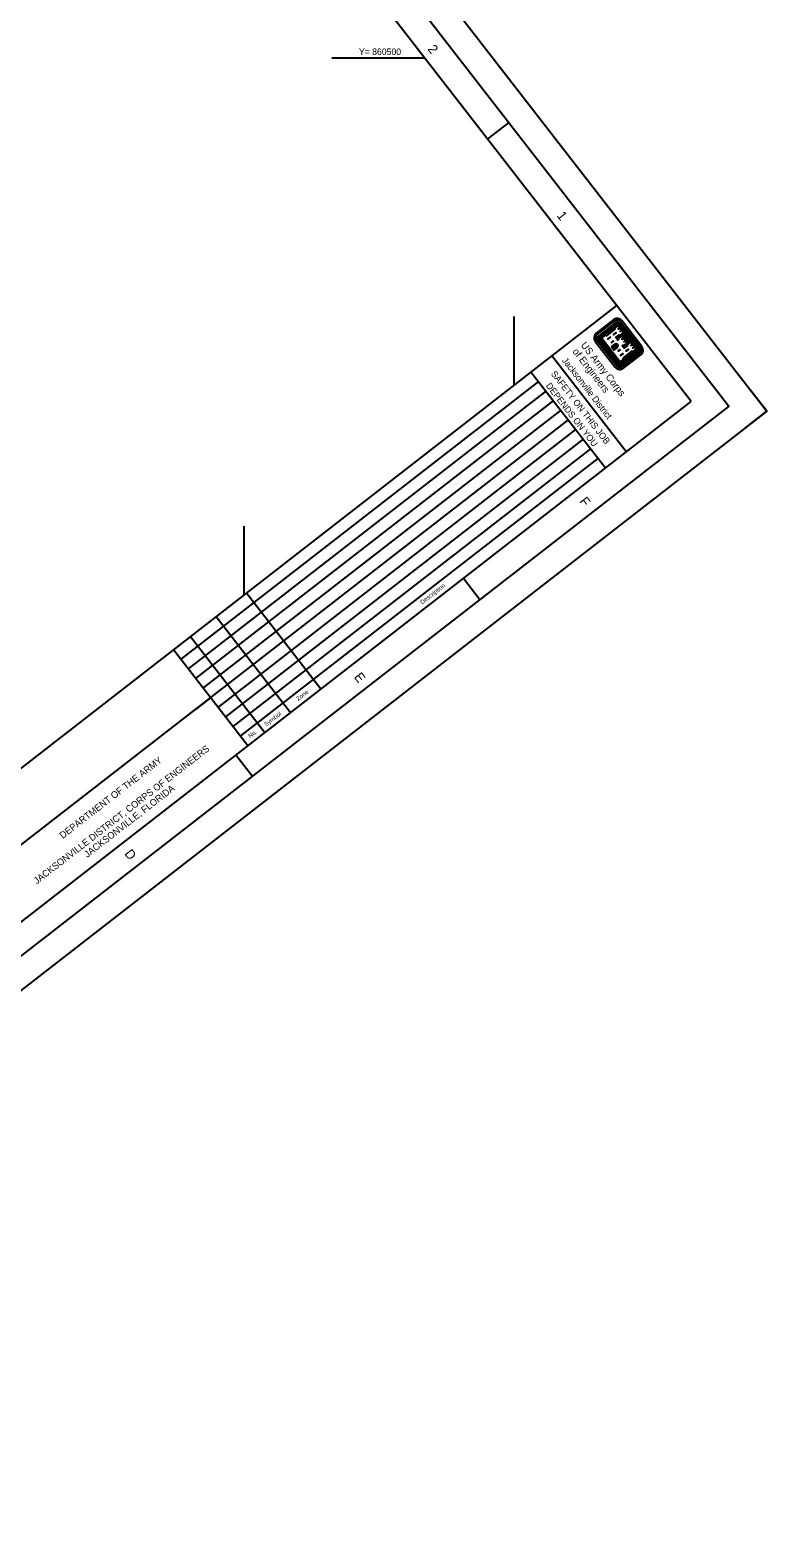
# Model space of a CAD drawing. Extents: x 575584 to 580968, y 857761 to 863322.
# Drawn here: x 579604 to 580968, y 857761 to 860551 of the extents above; entities that cross this region are included whole.
import ezdxf

# ---------------------------------------------------------------- set-up
doc = ezdxf.new("R2010")
doc.units = 0
for name, color, linetype in [('G-ANNO-NPLT', 7, 'Continuous'), ('G-ANNO-TEXT-LOGO', 7, 'Continuous'), ('G-ANNO-TEXT-TTLB', 7, 'Continuous'), ('G-ANNO-TTLB', 7, 'Continuous'), ('V-TOPO-COOR-STAT', 7, 'Continuous')]:
    doc.layers.add(name, color=color, linetype=linetype)

msp = doc.modelspace()

# ---------------------------------------------------------------- linework, layer by layer
at = {"layer": 'G-ANNO-NPLT'}
msp.add_lwpolyline([(578269.8, 863321.7), (580967.7, 859846), (578281.9, 857761.2), (575584, 861237)], close=True, dxfattribs=at)
msp.add_lwpolyline([(580928.2, 859815.3), (580967.7, 859846), (580937.1, 859885.5)], dxfattribs=at)
at = {"layer": 'G-ANNO-TEXT-LOGO'}
for p, q in [((580684.2, 860015.4), (580651.8, 859990.2)), ((580653.8, 859987.7), (580686.2, 860012.8)), ((580688.3, 860010.1), (580655.9, 859984.9)), ((580688.9, 860009.4), (580656.5, 859984.2)), ((580689.4, 860008.7), (580657, 859983.6)), ((580689.9, 860008), (580657.5, 859982.9)), ((580690.5, 860007.3), (580658.1, 859982.2)), ((580691, 860006.6), (580658.9, 859981.6)), ((580691.5, 860006), (580660.1, 859981.6)), ((580685.1, 860000.1), (580668.5, 859987.2)), ((580684.9, 859998.8), (580669.8, 859987.1)), ((580728.5, 859959.2), (580691.3, 860007.3)), ((580729.3, 859959.8), (580692, 860007.8)), ((580729.9, 859960.3), (580692.6, 860008.3)), ((580730.6, 859960.8), (580693.3, 860008.9)), ((580731.3, 859961.4), (580694, 860009.4)), ((580696.7, 860011.5), (580734, 859963.5)), ((580736.5, 859965.4), (580699.2, 860013.5)), ((580700.8, 859988), (580712.2, 859973.3)), ((580701.5, 859988.5), (580712.9, 859973.8)), ((580702.2, 859989.1), (580713.6, 859974.4)), ((580702.9, 859989.6), (580714.3, 859974.9)), ((580703.6, 859990.1), (580715, 859975.4)), ((580649.9, 859975.1), (580687.1, 859927.1)), ((580689.8, 859929.1), (580652.5, 859977.2)), ((580692.5, 859931.3), (580655.2, 859979.3)), ((580693.2, 859931.8), (580655.9, 859979.8)), ((580693.9, 859932.3), (580656.6, 859980.4)), ((580694.6, 859932.9), (580657.3, 859980.9)), ((580695.2, 859933.4), (580657.9, 859981.4)), ((580695.7, 859934.2), (580658.9, 859981.6)), ((580695.9, 859935.4), (580660.1, 859981.6)), ((580680.2, 859965.3), (580685.5, 859969.4)), ((580680.2, 859965.3), (580685.1, 859958.9)), ((580680.7, 859964.6), (580686, 859968.7)), ((580681.2, 859963.9), (580686.5, 859968)), ((580681.8, 859963.2), (580687.1, 859967.3)), ((580682.3, 859962.6), (580687.6, 859966.7)), ((580683, 859961.6), (580688.3, 859965.7)), ((580683.5, 859961), (580688.8, 859965.1)), ((580684.1, 859960.3), (580689.3, 859964.4)), ((580684.6, 859959.6), (580689.9, 859963.7)), ((580685.1, 859958.9), (580690.4, 859963.1)), ((580699.5, 859986.9), (580710.9, 859972.2)), ((580700.2, 859987.5), (580711.6, 859972.8)), ((580727.8, 859959.2), (580695.7, 859934.2)), ((580727.3, 859959.8), (580695.9, 859935.4)), ((580728.4, 859958.5), (580696, 859933.3)), ((580728.9, 859957.8), (580696.5, 859932.6)), ((580729.4, 859957.1), (580697, 859932)), ((580730, 859956.4), (580697.6, 859931.3)), ((580730.5, 859955.7), (580698.1, 859930.6)), ((580732.6, 859953), (580700.2, 859927.9)), ((580702.2, 859925.3), (580734.6, 859950.4)), ((580719.9, 859955), (580703.5, 859942.2)), ((580718.8, 859955.2), (580703.7, 859943.5))]:
    msp.add_line(p, q, dxfattribs=at)
for points in [[(580692, 860005.4), (580685.7, 860000.6), (580685.4, 859998.2), (580670.3, 859986.5), (580667.9, 859986.7), (580661, 859981.4), (580695.9, 859936.3), (580702.8, 859941.7), (580703.1, 859944.2), (580718.2, 859955.9), (580720.7, 859955.5), (580726.9, 859960.4), (580722.3, 859966.3), (580718.7, 859970.9), (580715.4, 859975.1), (580709.2, 859970.3), (580709, 859967.8), (580703.5, 859963.5), (580700.9, 859966.8), (580701.5, 859967.2), (580704, 859966.9), (580710.2, 859971.7), (580705.6, 859977.6), (580702, 859982.2), (580698.7, 859986.4), (580692.6, 859981.6), (580692.3, 859979.1), (580691.7, 859978.6), (580689.1, 859982), (580694.7, 859986.2), (580697.1, 859985.9), (580703.4, 859990.7), (580698.8, 859996.6), (580695.2, 860001.2), (580692, 860005.4)], [(580691.7, 860004.2), (580686.5, 860000.2), (580686.2, 859997.6), (580670.6, 859985.5), (580668, 859985.8), (580662.2, 859981.3), (580696.2, 859937.5), (580702, 859942.1), (580702.3, 859944.7), (580717.9, 859956.8), (580720.5, 859956.4), (580725.7, 859960.5), (580722.4, 859964.7), (580719.9, 859962.8), (580719.6, 859963.2), (580722.1, 859965.1), (580718.8, 859969.3), (580716.4, 859967.4), (580716.1, 859967.7), (580718.6, 859969.6), (580715.3, 859973.9), (580710.1, 859969.8), (580709.7, 859967.3), (580703.3, 859962.3), (580699.8, 859966.9), (580701.3, 859968.1), (580703.8, 859967.8), (580709, 859971.8), (580705.7, 859976.1), (580703.3, 859974.2), (580703, 859974.5), (580705.5, 859976.4), (580702.2, 859980.7), (580699.7, 859978.8), (580699.4, 859979.2), (580701.9, 859981.1), (580698.6, 859985.3), (580693.4, 859981.2), (580693.1, 859978.7), (580691.6, 859977.5), (580688, 859982.1), (580694.4, 859987.1), (580696.9, 859986.7), (580702.2, 859990.8), (580698.9, 859995), (580696.5, 859993.1), (580696.1, 859993.5), (580698.6, 859995.4), (580695.3, 859999.6), (580692.8, 859997.7), (580692.6, 859998.1), (580695, 860000), (580691.7, 860004.2)], [(580688.3, 859991.2), (580683.7, 859987.6), (580684.1, 859987.2), (580688.7, 859990.7), (580688.3, 859991.2)], [(580677.8, 859983), (580673.1, 859979.4), (580673.5, 859978.9), (580678.2, 859982.6), (580677.8, 859983)], [(580683.4, 859975.8), (580680.2, 859973.2), (580680.5, 859972.9), (580683.7, 859975.4), (580683.4, 859975.8)], [(580695.6, 859985.2), (580694.9, 859985.3), (580690.4, 859981.8), (580691.6, 859980.3), (580691.8, 859982.1), (580695.7, 859985.2)], [(580708.2, 859968.9), (580708.1, 859968.2), (580703.6, 859964.7), (580702.5, 859966.2), (580704.3, 859966), (580708.3, 859969.1)], [(580712.2, 859960.5), (580707.6, 859956.9), (580707.3, 859957.3), (580711.9, 859960.8), (580712.2, 859960.5)], [(580696.1, 859959.5), (580692.8, 859957), (580692.5, 859957.4), (580695.8, 859959.9), (580696.1, 859959.5)], [(580701.7, 859952.3), (580697, 859948.7), (580696.7, 859949.1), (580701.3, 859952.7), (580701.7, 859952.3)]]:
    msp.add_lwpolyline(points, dxfattribs=at)
for centre, major_axis, start_param, end_param in [((580690.8, 860006.9), (6.57, -8.46), 1.57078, 3.141576), ((580658.4, 859981.7), (-6.57, 8.46), 6.28317, 7.853966), ((580690.8, 860006.9), (4.59, -5.92), 1.57078, 3.141576), ((580690.8, 860006.9), (2.46, -3.17), 1.57078, 3.141576), ((580690.8, 860006.9), (1.93, -2.49), 1.57078, 3.141576), ((580690.8, 860006.9), (1.4, -1.8), 1.57078, 3.141576), ((580690.8, 860006.9), (0.87, -1.12), 1.57078, 3.141576), ((580690.8, 860006.9), (0.335, -0.431), 1.57078, 3.141576), ((580658.4, 859981.7), (-4.59, 5.92), 6.28317, 7.853966), ((580658.4, 859981.7), (-2.46, 3.17), 6.28317, 7.853966), ((580658.4, 859981.7), (-1.93, 2.49), 6.28317, 7.853966), ((580658.4, 859981.7), (-1.4, 1.8), 6.28317, 7.853966), ((580658.4, 859981.7), (-0.87, 1.12), 6.28317, 7.853966), ((580658.4, 859981.7), (-0.335, 0.431), 6.28317, 7.853966), ((580688.5, 859964.8), (-3.41, 4.39), 4.985832, 6.214359), ((580688.5, 859964.8), (-2.87, 3.7), 4.947465, 6.21436), ((580688.5, 859964.8), (-2.34, 3.02), 4.947465, 6.21436), ((580688.5, 859964.8), (-1.81, 2.33), 4.947465, 6.21436), ((580688.5, 859964.8), (-1.28, 1.64), 4.947465, 6.214359), ((580686.7, 859967.1), (1.28, -1.64), 0.068794, 1.335689), ((580686.7, 859967.1), (1.81, -2.33), 0.068794, 1.335689), ((580686.7, 859967.1), (2.34, -3.02), 0.068795, 1.335689), ((580686.7, 859967.1), (2.87, -3.7), 0.068795, 1.335689), ((580686.7, 859967.1), (3.41, -4.39), 0.068795, 1.29842), ((580728, 859958.9), (1.4, -1.8), 6.283169, 7.853965), ((580728, 859958.9), (1.93, -2.49), 6.283169, 7.853965), ((580728, 859958.9), (2.46, -3.17), 6.283169, 7.853965), ((580728, 859958.9), (4.59, -5.92), 6.28317, 7.853966), ((580728, 859958.9), (6.57, -8.46), 6.283169, 7.853965), ((580695.6, 859933.8), (1.4, -1.8), 4.712373, 6.28317), ((580695.6, 859933.8), (0.87, -1.12), 4.712373, 6.28317), ((580695.6, 859933.8), (0.335, -0.431), 4.712373, 6.28317), ((580728, 859958.9), (0.335, -0.431), 6.283169, 7.853965), ((580728, 859958.9), (0.87, -1.12), 6.283169, 7.853965), ((580695.6, 859933.8), (6.57, -8.46), 4.712373, 6.28317), ((580695.6, 859933.8), (-4.59, 5.92), 1.570781, 3.141577), ((580695.6, 859933.8), (2.46, -3.17), 4.712373, 6.28317), ((580695.6, 859933.8), (1.93, -2.49), 4.712373, 6.28317)]:
    msp.add_ellipse(centre, major_axis=major_axis, ratio=0.99964, start_param=start_param, end_param=end_param, dxfattribs=at)
at = {"layer": 'G-ANNO-TTLB'}
for p, q in [((580489.8, 860380.1), (580450.3, 860349.5)), ((580689.4, 860041.4), (578161.6, 858079.3)), ((580570, 859948.7), (580707.9, 859770.9)), ((580530.8, 859919), (580668.8, 859741.3)), ((580544.9, 859900.9), (579882.9, 859387.1)), ((580558.7, 859883.1), (579896.7, 859369.4)), ((580572.5, 859865.4), (579910.5, 859351.6)), ((580586.2, 859847.6), (579924.3, 859333.8)), ((580600, 859829.8), (579938.1, 859316)), ((580613.8, 859812), (579951.9, 859298.3)), ((580627.6, 859794.3), (579965.7, 859280.5)), ((580641.4, 859776.5), (579979.5, 859262.7)), ((580655.2, 859758.7), (579993.3, 859244.9)), ((580436.6, 859497), (580406, 859536.5)), ((580004.4, 859509.6), (580142.3, 859331.9)), ((579948.1, 859466), (580086.1, 859288.2)), ((579869.3, 859404.8), (580007.2, 859227)), ((579900.8, 859429.2), (580038.7, 859251.4)), ((579258.8, 858789.3), (579938.3, 859315.9)), ((579938.3, 859315.9), (579910.3, 859294.2)), ((580015.4, 859170), (579984.7, 859209.5))]:
    msp.add_line(p, q, dxfattribs=at)
for points in [[(575654.1, 861228.1), (578290.7, 857831.4), (580897.6, 859854.8), (578260.9, 863251.6)], [(580827.4, 859863.6), (578298.1, 863122.2), (575770.3, 861160), (578299.6, 857901.5)]]:
    msp.add_lwpolyline(points, close=True, dxfattribs=at)
at = {"layer": 'V-TOPO-COOR-STAT'}
for p, q in [((580162.6, 860500), (580333.5, 860500)), ((580500, 859894.4), (580500, 860021)), ((580000, 859506.3), (580000, 859632.9))]:
    msp.add_line(p, q, dxfattribs=at)

# ---------------------------------------------------------------- texts
at = {"layer": 'G-ANNO-TEXT-TTLB'}
for s, height, rotation, p in [('of Engineers', 13.086, 307.8192, (580607.1, 859956)), ('US Army Corps', 13.086, 307.8192, (580622.4, 859967.9)), ('Jacksonville District', 11.9, 307.8192, (580587.7, 859939.7)), ('SAFETY ON THIS JOB', 11.9, 307.8192, (580567.3, 859914.8)), ('DEPENDS ON YOU', 11.9, 307.8192, (580558, 859892.7)), ('Description', 8, 37.8192, (580329.7, 859487.9)), ('Zone', 8, 37.8192, (580100.2, 859309.4)), ('Symbol', 8, 37.8192, (580040.7, 859261.7)), ('No.', 8, 37.8192, (580011.5, 859240.4)), ('JACKSONVILLE DISTRICT, CORPS OF ENGINEERS', 12.5, 37.8192, (579616.5, 858970.1)), ('DEPARTMENT OF THE ARMY', 12.5, 37.8192, (579664.4, 859054.1)), ('JACKSONVILLE, FLORIDA', 12.5, 37.8192, (579709.9, 859019.2))]:
    msp.add_text(s, height=height, rotation=rotation, dxfattribs=at).set_placement(p)
at = {"layer": 'G-ANNO-TTLB'}
for s, p in [('2', (580338.9, 860515.6)), ('1', (580578, 860207.5)), ('F', (580619.9, 859678.8)), ('E', (580202.6, 859353.9)), ('D', (579777.7, 859026.9))]:
    msp.add_text(s, height=17.5, rotation=307.8192, dxfattribs=at).set_placement(p)
at = {"layer": 'V-TOPO-COOR-STAT'}
msp.add_text('Y= 860500', height=12, dxfattribs=at).set_placement((580212.6, 860505))

doc.saveas('drawing.dxf')
